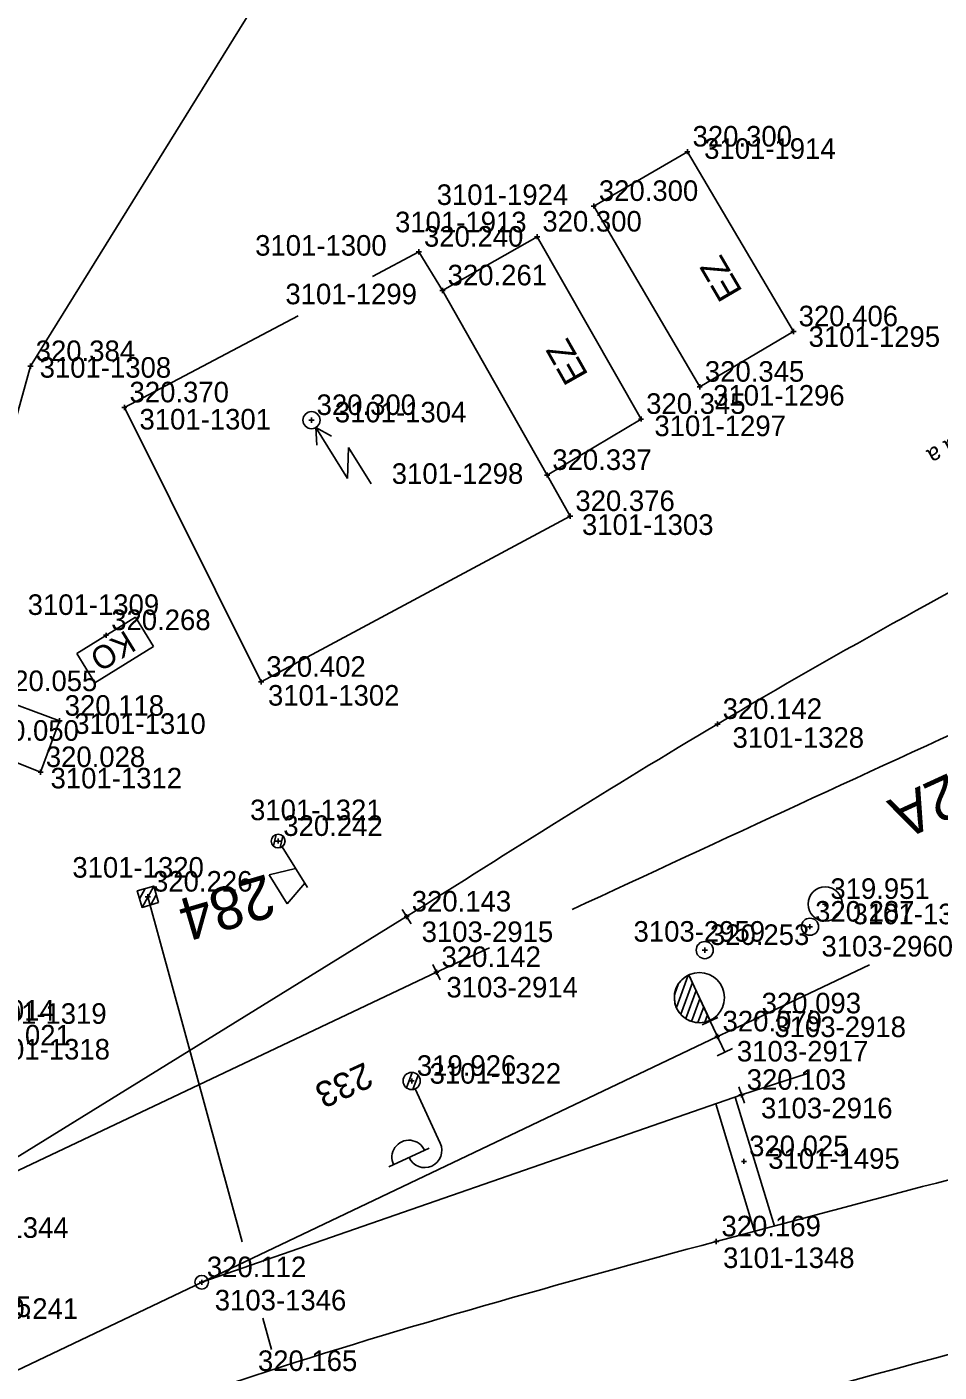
# Model space of a CAD drawing. Extents: x -821875 to -821475, y -1070280 to -1069975.
# Drawn here: x -821775.51 to -821748.89, y -1070211.76 to -1070172.51 of the extents above; entities that cross this region are included whole.
import ezdxf

# ---------------------------------------------------------------- set-up
doc = ezdxf.new("R2010")
doc.units = 0
for name, color, linetype in [('Vrstva 1', 7, 'Continuous'), ('Vrstva 11', 7, 'Continuous'), ('Vrstva 17', 7, 'Continuous'), ('Vrstva 2', 7, 'Continuous'), ('Vrstva 23', 7, 'Continuous'), ('Vrstva 25', 7, 'Continuous'), ('Vrstva 28', 7, 'Continuous'), ('Vrstva 3', 7, 'Continuous'), ('Vrstva 33', 7, 'Continuous'), ('Vrstva 36', 7, 'Continuous'), ('Vrstva 43', 7, 'Continuous'), ('Vrstva 49', 7, 'Continuous'), ('Vrstva 6', 7, 'Continuous'), ('Vrstva 60', 7, 'Continuous'), ('Vrstva 61', 7, 'Continuous'), ('Vrstva 7', 7, 'Continuous')]:
    doc.layers.add(name, color=color, linetype=linetype)

# ---------------------------------------------------------------- blocks, each defined once
blk = doc.blocks.new('BOD')
at = {"layer": 'Vrstva 3'}
for p, q in [((-0.15, 0), (0.15, 0)), ((0, -0.15), (0, 0.15))]:
    blk.add_line(p, q, dxfattribs=at)

msp = doc.modelspace()

# ---------------------------------------------------------------- linework, layer by layer
at = {"layer": 'Vrstva 1'}
for p, q in [((-821762.01, -1070199.374), (-821763.559, -1070200.088)), ((-821752.732, -1070203.045), (-821754.655, -1070203.671))]:
    msp.add_line(p, q, dxfattribs=at)
for points in [[(-821679.285, -1070162.663), (-821695.528, -1070167.095), (-821716.799, -1070174.043), (-821730.799, -1070179.932), (-821744.379, -1070186.736), (-821755.356, -1070192.851), (-821764.427, -1070198.469)], [(-821677.113, -1070166.912), (-821699.427, -1070173.07), (-821715.575, -1070178.704), (-821729.749, -1070184.723), (-821746.361, -1070192.156), (-821759.601, -1070198.262)], [(-821710.276, -1070200.761), (-821741.264, -1070209.238), (-821760.235, -1070214.402), (-821776.338, -1070219.041), (-821794.464, -1070225.772), (-821811.866, -1070233.595), (-821823.5, -1070239.204)], [(-821742.542, -1070204.561), (-821755.391, -1070207.946), (-821768.915, -1070211.875), (-821773.964, -1070213.578)], [(-821709.336, -1070205.287), (-821731.872, -1070211.395), (-821757.763, -1070218.461), (-821767.367, -1070221.229)]]:
    msp.add_spline(points, degree=3, dxfattribs=at)
at = {"layer": 'Vrstva 11'}
for p, q in [((-821772.059, -1070197.652), (-821772.219, -1070197.946)), ((-821771.805, -1070197.579), (-821772.143, -1070198.198)), ((-821771.975, -1070197.888), (-821769.226, -1070207.957)), ((-821771.73, -1070197.833), (-821771.888, -1070198.123)), ((-821768.618, -1070210.187), (-821768.368, -1070211.101))]:
    msp.add_line(p, q, dxfattribs=at)
msp.add_lwpolyline([(-821771.664, -1070198.057), (-821772.144, -1070198.199), (-821772.286, -1070197.719), (-821771.806, -1070197.577)], close=True, dxfattribs=at)
msp.add_lwpolyline([(-821771.664, -1070198.057), (-821772.144, -1070198.199), (-821772.286, -1070197.719), (-821771.806, -1070197.577), (-821771.664, -1070198.057)], dxfattribs=at)
at = {"layer": 'Vrstva 17'}
for points in [[(-821765.425, -1070179.788), (-821764.071, -1070179.072), (-821763.38, -1070180.2)], [(-821772.661, -1070183.613), (-821767.595, -1070180.935)], [(-821760.326, -1070185.586), (-821759.653, -1070186.785), (-821768.67, -1070191.621), (-821772.661, -1070183.613)]]:
    msp.add_lwpolyline(points, dxfattribs=at)
at = {"layer": 'Vrstva 2'}
for p, q in [((-821764.559, -1070198.256), (-821764.295, -1070198.682)), ((-821763.666, -1070199.862), (-821763.452, -1070200.314)), ((-821756.555, -1070201.119), (-821756.208, -1070200.177)), ((-821756.431, -1070201.317), (-821756.089, -1070200.387)), ((-821756.19, -1070200.167), (-821755.577, -1070201.496)), ((-821756.19, -1070200.168), (-821756.19, -1070200.167)), ((-821756.189, -1070200.172), (-821755.575, -1070201.501)), ((-821756.606, -1070200.721), (-821756.504, -1070200.444)), ((-821756.281, -1070201.445), (-821755.979, -1070200.625)), ((-821756.113, -1070201.525), (-821755.87, -1070200.863)), ((-821755.929, -1070201.56), (-821755.76, -1070201.1)), ((-821755.726, -1070201.545), (-821755.65, -1070201.338)), ((-821755.576, -1070201.501), (-821755.359, -1070201.967)), ((-821754.737, -1070203.435), (-821754.573, -1070203.907))]:
    msp.add_line(p, q, dxfattribs=at)
for points in [[(-821783.916, -1070210.505), (-821764.427, -1070198.469)], [(-821755.359, -1070201.967), (-821754.218, -1070201.44), (-821750.917, -1070199.873)], [(-821778.563, -1070207.199), (-821763.559, -1070200.088)], [(-821779.893, -1070213.645), (-821778.741, -1070213.109), (-821755.359, -1070201.967)], [(-821770.406, -1070209.137), (-821754.655, -1070203.671)]]:
    msp.add_lwpolyline(points, dxfattribs=at)
for centre, radius in [((-821755.884, -1070200.832), 0.731), ((-821770.406, -1070209.137), 0.2)]:
    msp.add_circle(centre, radius, dxfattribs=at)
msp.add_arc((-821755.884, -1070200.832), 0.732, 114.8087, 294.7695, dxfattribs=at)
at = {"layer": 'Vrstva 23'}
msp.add_lwpolyline([(-821776.501, -1070192.039), (-821774.553, -1070192.757), (-821775.104, -1070194.254), (-821777.038, -1070193.488), (-821776.501, -1070192.039)], dxfattribs=at)
at = {"layer": 'Vrstva 25'}
for p, q in [((-821767.181, -1070183.97), (-821767.225, -1070183.996)), ((-821766.15, -1070185.684), (-821767.071, -1070184.196)), ((-821766.622, -1070184.447), (-821767.071, -1070184.196)), ((-821767.071, -1070184.196), (-821767.047, -1070184.71)), ((-821766.12, -1070184.783), (-821766.15, -1070185.684)), ((-821765.461, -1070185.845), (-821766.12, -1070184.783)), ((-821764.261, -1070203.015), (-821764.427, -1070203.463)), ((-821764.091, -1070203.097), (-821764.245, -1070203.509)), ((-821764.174, -1070203.49), (-821763.446, -1070205.081)), ((-821763.764, -1070205.227), (-821764.945, -1070205.768))]:
    msp.add_line(p, q, dxfattribs=at)
for centre in [(-821767.203, -1070183.983), (-821764.278, -1070203.263), (-821764.278, -1070203.263)]:
    msp.add_circle(centre, 0.25, dxfattribs=at)
for centre, start, end in [((-821764.357, -1070205.492), 23.9023, 205.3074), ((-821763.9, -1070205.29), 204.6049, 24.6049)]:
    msp.add_arc(centre, 0.5, start, end, dxfattribs=at)
at = {"layer": 'Vrstva 28'}
for p, q in [((-821772.339, -1070189.728), (-821774.053, -1070190.79)), ((-821771.808, -1070190.585), (-821772.339, -1070189.728)), ((-821773.522, -1070191.647), (-821771.808, -1070190.585)), ((-821774.053, -1070190.79), (-821773.522, -1070191.647)), ((-821752.684, -1070198.764), (-821752.634, -1070198.764)), ((-821755.753, -1070199.445), (-821755.703, -1070199.445))]:
    msp.add_line(p, q, dxfattribs=at)
for centre in [(-821752.659, -1070198.764), (-821755.728, -1070199.445)]:
    msp.add_circle(centre, 0.25, dxfattribs=at)
at = {"layer": 'Vrstva 3'}
for p, q in [((-821755.8, -1070201.623), (-821755.348, -1070201.408)), ((-821755.574, -1070201.515), (-821755.144, -1070202.419)), ((-821755.37, -1070202.526), (-821754.918, -1070202.311))]:
    msp.add_line(p, q, dxfattribs=at)
at = {"layer": 'Vrstva 33'}
for p, q in [((-821768.237, -1070196.074), (-821768.314, -1070196.407)), ((-821768.04, -1070196.116), (-821768.12, -1070196.455)), ((-821767.322, -1070197.616), (-821768.06, -1070196.428)), ((-821768.434, -1070197.246), (-821767.665, -1070197.063)), ((-821767.907, -1070198.096), (-821768.434, -1070197.246)), ((-821767.401, -1070197.488), (-821767.907, -1070198.096))]:
    msp.add_line(p, q, dxfattribs=at)
for radius in [0.201, 0.2]:
    msp.add_circle((-821768.175, -1070196.264), radius, dxfattribs=at)
at = {"layer": 'Vrstva 36'}
for points in [[(-821758.968, -1070177.737), (-821756.234, -1070176.15), (-821753.139, -1070181.395), (-821755.875, -1070183.012), (-821758.968, -1070177.737)], [(-821763.38, -1070180.2), (-821760.616, -1070178.631), (-821757.588, -1070183.95), (-821760.326, -1070185.586), (-821763.38, -1070180.2)]]:
    msp.add_lwpolyline(points, dxfattribs=at)
at = {"layer": 'Vrstva 43'}
msp.add_circle((-821752.214, -1070198.101), 0.5, dxfattribs=at)
at = {"layer": 'Vrstva 49'}
msp.add_lwpolyline([(-821777.907, -1070191.463), (-821775.399, -1070182.41), (-821768.529, -1070171.311), (-821736.653, -1070158.01)], dxfattribs=at)
at = {"layer": 'Vrstva 7'}
for p, q in [((-821754.275, -1070207.652), (-821755.408, -1070203.932)), ((-821753.694, -1070207.499), (-821754.841, -1070203.736))]:
    msp.add_line(p, q, dxfattribs=at)

# ---------------------------------------------------------------- block references
at = {"layer": 'Vrstva 60', "xscale": 0.5, "yscale": 0.5}
for p in [(-821756.234, -1070176.15), (-821758.968, -1070177.737), (-821760.616, -1070178.631), (-821764.071, -1070179.072), (-821763.38, -1070180.2), (-821753.139, -1070181.395), (-821775.399, -1070182.41), (-821755.875, -1070183.012), (-821772.661, -1070183.613), (-821767.203, -1070183.983), (-821757.588, -1070183.95), (-821760.326, -1070185.586), (-821759.653, -1070186.785), (-821773.196, -1070190.259), (-821768.67, -1070191.621), (-821774.553, -1070192.757), (-821755.356, -1070192.851), (-821775.104, -1070194.254), (-821768.175, -1070196.264), (-821771.975, -1070197.888), (-821752.214, -1070198.101), (-821764.427, -1070198.469), (-821752.659, -1070198.764), (-821755.728, -1070199.445), (-821763.559, -1070200.088), (-821754.218, -1070201.44), (-821755.359, -1070201.967), (-821764.278, -1070203.263), (-821754.655, -1070203.671), (-821754.584, -1070205.608), (-821755.391, -1070207.946), (-821770.406, -1070209.137)]:
    msp.add_blockref('BOD', p, dxfattribs=at)

# ---------------------------------------------------------------- texts
at = {"layer": 'Vrstva 11'}
for s, rotation, p in [('282A', 204.6049, (-821746.907, -1070193.486)), ('284', 196.4272, (-821768.508, -1070197.218))]:
    msp.add_text(s, height=1.25, rotation=rotation, dxfattribs=at).set_placement(p)
at = {"layer": 'Vrstva 25'}
msp.add_text('233', height=0.75, rotation=204.6049, dxfattribs=at).set_placement((-821765.643, -1070202.701))
at = {"layer": 'Vrstva 28'}
msp.add_text('KO', height=0.672, rotation=211.7714, dxfattribs=at).set_placement((-821772.622, -1070190.093))
at = {"layer": 'Vrstva 36'}
for rotation, p in [(120.3853, (-821754.613, -1070180.222)), (119.5543, (-821759.111, -1070182.66))]:
    msp.add_text('EZ', height=0.75, rotation=rotation, dxfattribs=at).set_placement(p)
at = {"layer": 'Vrstva 6'}
msp.add_text('  a a a a a', height=0.5, rotation=208.4248, dxfattribs=at).set_placement((-821746.676, -1070183.466))
at = {"layer": 'Vrstva 60'}
for s, p in [('3101-1914', (-821755.746, -1070176.359)), ('3101-1924', (-821763.549, -1070177.705)), ('3101-1913', (-821764.764, -1070178.502)), ('3101-1300', (-821768.846, -1070179.184)), ('3101-1299', (-821767.963, -1070180.602)), ('3101-1295', (-821752.699, -1070181.845)), ('3101-1308', (-821775.133, -1070182.745)), ('3101-1296', (-821755.484, -1070183.559)), ('3101-1304', (-821766.522, -1070184.048)), ('3101-1301', (-821772.221, -1070184.256)), ('3101-1297', (-821757.197, -1070184.449)), ('3101-1298', (-821764.86, -1070185.842)), ('3101-1303', (-821759.31, -1070187.332)), ('3101-1309', (-821775.483, -1070189.666)), ('3101-1302', (-821768.472, -1070192.312)), ('3101-1310', (-821774.124, -1070193.137)), ('3101-1328', (-821754.917, -1070193.542)), ('3101-1312', (-821774.815, -1070194.727)), ('3101-1321', (-821768.994, -1070195.654)), ('3101-1320', (-821774.179, -1070197.331)), ('3101-1324', (-821751.415, -1070198.691)), ('3103-2915', (-821763.987, -1070199.209)), ('3103-2959', (-821757.806, -1070199.199)), ('3103-2960', (-821752.323, -1070199.632)), ('3103-2914', (-821763.265, -1070200.827)), ('3101-1319', (-821777.016, -1070201.596)), ('3103-2918', (-821753.696, -1070201.983)), ('3101-1318', (-821776.919, -1070202.638)), ('3103-2917', (-821754.791, -1070202.695)), ('3101-1322', (-821763.756, -1070203.342)), ('3103-2916', (-821754.087, -1070204.353)), ('3101-1495', (-821753.877, -1070205.826)), ('3103-1344', (-821778.125, -1070207.841)), ('3101-1348', (-821755.194, -1070208.721)), ('3103-1346', (-821770.024, -1070209.958)), ('3103-2955', (-821779.215, -1070210.149))]:
    msp.add_text(s, height=0.6, dxfattribs=at).set_placement(p)
at = {"layer": 'Vrstva 61'}
for s, p in [('320.300', (-821756.084, -1070176)), ('320.300', (-821758.818, -1070177.587)), ('320.300', (-821760.466, -1070178.481)), ('320.240', (-821763.921, -1070178.922)), ('320.261', (-821763.23, -1070180.05)), ('320.406', (-821752.989, -1070181.245)), ('320.384', (-821775.249, -1070182.26)), ('320.345', (-821755.725, -1070182.862)), ('320.370', (-821772.511, -1070183.463)), ('320.300', (-821767.053, -1070183.833)), ('320.345', (-821757.438, -1070183.8)), ('320.337', (-821760.176, -1070185.436)), ('320.376', (-821759.503, -1070186.635)), ('320.268', (-821773.046, -1070190.109)), ('320.402', (-821768.52, -1070191.471)), ('320.055', (-821776.351, -1070191.889)), ('320.118', (-821774.403, -1070192.607)), ('320.142', (-821755.206, -1070192.701)), ('320.050', (-821776.888, -1070193.338)), ('320.028', (-821774.954, -1070194.104)), ('320.242', (-821768.025, -1070196.114)), ('320.226', (-821771.825, -1070197.738)), ('319.951', (-821752.064, -1070197.951)), ('320.143', (-821764.277, -1070198.319)), ('320.287', (-821752.509, -1070198.614)), ('320.253', (-821755.578, -1070199.295)), ('320.142', (-821763.409, -1070199.938)), ('320.093', (-821754.068, -1070201.29)), ('320.014', (-821777.593, -1070201.5)), ('320.079', (-821755.209, -1070201.817)), ('320.021', (-821777.124, -1070202.227)), ('319.926', (-821764.128, -1070203.113)), ('320.103', (-821754.505, -1070203.521)), ('320.025', (-821754.434, -1070205.458)), ('320.169', (-821755.241, -1070207.796)), ('320.112', (-821770.256, -1070208.987)), ('320.241', (-821776.91, -1070210.204)), ('320.165', (-821768.765, -1070211.725))]:
    msp.add_text(s, height=0.6, dxfattribs=at).set_placement(p)

doc.saveas('drawing.dxf')
